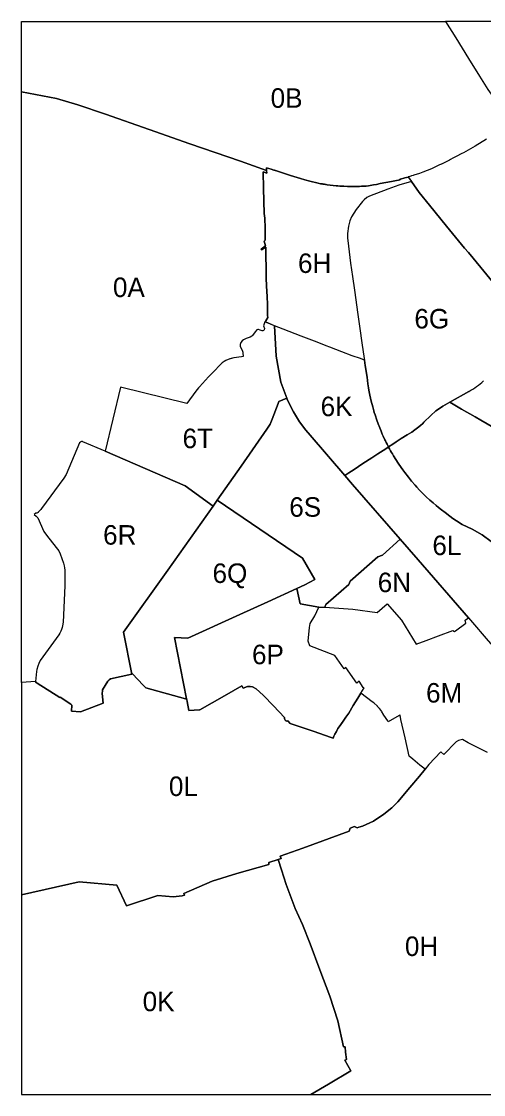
# Model space of a CAD drawing. Extents: x 152750 to 166250, y 378996 to 390000.
# Drawn here: x 152750 to 157492, y 379000 to 390000 of the extents above; entities that cross this region are included whole.
import ezdxf

# ---------------------------------------------------------------- set-up
doc = ezdxf.new("R2010")
doc.units = 0
doc.layers.add('BLT_Nummers', color=7, linetype='Continuous')
doc.layers.add('BLT_Shapes', color=7, linetype='Continuous')

msp = doc.modelspace()

# ---------------------------------------------------------------- linework, layer by layer
at = {"layer": 'BLT_Shapes'}
for p, q in [((163503, 390000), (157101, 390000)), ((157522, 388793), (157405, 388722)), ((157153, 388585), (157141, 388579)), ((157178, 388598), (157153, 388585)), ((156717, 388406), (156752, 388358)), ((156831, 388247), (156752, 388358)), ((155248, 386922), (155242, 386902)), ((155345, 386881), (155248, 386922)), ((155437, 386846), (155345, 386881)), ((155363, 386570), (155345, 386881)), ((155098, 386765), (155055, 386750)), ((155148, 386820), (155122, 386782)), ((155167, 386840), (155148, 386820)), ((155176, 386843), (155167, 386840)), ((155244, 386852), (155239, 386839)), ((155028, 386735), (155016, 386725)), ((155055, 386750), (155028, 386735)), ((155022, 386601), (155024, 386570)), ((154794, 386485), (154719, 386407)), ((154797, 386488), (154794, 386485)), ((154719, 386407), (154671, 386356)), ((153766, 386250), (153608, 385595)), ((156315, 386222), (156311, 386244)), ((157342, 386207), (157147, 386097)), ((157147, 386097), (157342, 386207)), ((156378, 385968), (156371, 385993)), ((157264, 386027), (157147, 386097)), ((157404, 385948), (157264, 386027)), ((157465, 385912), (157404, 385948)), ((156788, 385813), (156815, 385834)), ((156815, 385834), (156845, 385859)), ((153360, 385692), (153355, 385689)), ((153380, 385692), (153375, 385694)), ((153608, 385595), (153380, 385692)), ((156517, 385639), (156503, 385666)), ((156517, 385639), (156561, 385667)), ((156561, 385667), (156595, 385692)), ((153608, 385595), (154431, 385239)), ((156518, 385637), (156517, 385639)), ((153208, 385355), (153184, 385319)), ((156109, 385372), (156068, 385345)), ((156148, 385253), (156068, 385345)), ((156165, 385407), (156109, 385372)), ((156664, 385403), (156647, 385427)), ((154431, 385239), (154716, 385033)), ((156636, 384694), (156148, 385253)), ((156866, 385166), (156836, 385196)), ((156904, 385128), (156866, 385166)), ((156942, 385093), (156904, 385128)), ((154253, 384374), (154716, 385033)), ((154758, 385093), (154716, 385033)), ((154716, 385033), (154758, 385093)), ((155633, 384497), (154758, 385093)), ((154758, 385093), (155633, 384497)), ((156975, 385065), (156942, 385093)), ((152899, 384961), (152881, 384947)), ((152881, 384947), (152902, 384929)), ((152905, 384959), (152899, 384961)), ((152902, 384929), (152915, 384915)), ((152909, 384960), (152905, 384959)), ((152915, 384915), (152919, 384911)), ((157374, 384794), (157273, 384844)), ((157476, 384737), (157374, 384794)), ((156636, 384694), (156822, 384481)), ((156822, 384481), (156636, 384694)), ((157569, 384670), (157476, 384737)), ((156822, 384481), (157337, 383887)), ((157337, 383887), (156822, 384481)), ((153190, 384420), (153193, 384398)), ((153193, 384398), (153195, 384374)), ((153195, 384374), (153194, 384216)), ((153796, 383739), (154253, 384374)), ((156399, 383941), (156504, 384030)), ((154456, 383679), (154991, 383922)), ((155802, 383997), (155864, 383995)), ((155864, 383995), (156149, 383975)), ((156149, 383975), (156399, 383941)), ((157204, 383755), (157311, 383832)), ((157304, 383862), (157337, 383887)), ((157311, 383832), (157304, 383862)), ((157337, 383887), (157398, 383816)), ((153168, 383787), (153162, 383768)), ((153883, 383310), (153796, 383739)), ((157194, 383748), (157204, 383755)), ((152904, 383336), (152894, 383234)), ((153651, 383252), (153663, 383260)), ((153663, 383260), (153883, 383310)), ((153883, 383310), (153891, 383312)), ((155104, 383207), (155104, 383207)), ((153589, 383012), (153579, 383112)), ((154433, 383058), (154445, 383055)), ((153356, 382923), (153589, 383012))]:
    msp.add_line(p, q, dxfattribs=at)
for points in [[(157522, 388793), (157405, 388722), (157285, 388654), (157270, 388647), (157212, 388616), (157178, 388598), (157153, 388585), (157141, 388579), (157127, 388572), (157059, 388537), (157041, 388529), (156998, 388509), (156956, 388490), (156869, 388456), (156833, 388443), (156778, 388424), (156769, 388421), (156769, 388421), (156753, 388416), (156747, 388415), (156736, 388411), (156721, 388407), (156721, 388407), (156717, 388406), (156718, 388405), (156701, 388400), (156685, 388396), (156641, 388384), (156632, 388382), (156636, 388376), (156581, 388368), (156548, 388361), (156488, 388350), (156430, 388338), (156394, 388330), (156364, 388324), (156329, 388319), (156312, 388316), (156287, 388313), (156277, 388312), (156258, 388311), (156239, 388310), (156220, 388309), (156201, 388308), (156191, 388308), (156180, 388307), (156170, 388307), (156159, 388307), (156128, 388307), (156118, 388307), (156097, 388308), (156059, 388310), (156016, 388313), (155998, 388314), (155981, 388316), (155886, 388327), (155877, 388328), (155869, 388329), (155861, 388331), (155852, 388332), (155844, 388333), (155839, 388334), (155820, 388337), (155795, 388342), (155766, 388348), (155738, 388355), (155708, 388362), (155657, 388377), (155614, 388389), (155511, 388422), (155397, 388460), (155377, 388466), (155356, 388471), (155352, 388473), (155345, 388474), (155340, 388476), (155311, 388485), (155266, 388501), (155266, 388473), (154997, 388567), (154479, 388747), (154060, 388894), (153611, 389049), (153328, 389146), (153110, 389210), (152750, 389278), (152750, 390000), (157101, 390000), (157206, 389831), (157337, 389621), (157450, 389440), (157537, 389302)], [(157101, 390000), (157206, 389831), (157337, 389621), (157450, 389440), (157537, 389302), (157569, 389253), (157631, 389159), (157637, 389146), (157655, 389117), (157768, 388950)], [(157405, 388722), (157285, 388654), (157270, 388647), (157212, 388616), (157178, 388598)], [(157041, 388529), (157007, 388513), (156998, 388509), (156956, 388490)], [(157141, 388579), (157127, 388572), (157059, 388537), (157057, 388536), (157041, 388529)], [(156736, 388411), (156736, 388411), (156721, 388407), (156721, 388407), (156717, 388406)], [(156769, 388421), (156769, 388421), (156753, 388416), (156747, 388415), (156736, 388411)], [(156833, 388443), (156778, 388424), (156769, 388421)], [(156956, 388490), (156869, 388456), (156833, 388443)], [(156752, 388358), (156624, 388322), (156510, 388281), (156321, 388210), (156293, 388195), (156265, 388172), (156248, 388156), (156184, 388074), (156136, 387996), (156121, 387955), (156106, 387903), (156096, 387828), (156097, 387781), (156105, 387697), (156128, 387524), (156147, 387386), (156167, 387245), (156202, 386995), (156223, 386853), (156244, 386706), (156268, 386546), (156270, 386528)], [(156752, 388358), (156831, 388247), (156937, 388117), (157112, 387900), (157297, 387677), (157336, 387630), (157463, 387477), (157647, 387254), (157840, 387022), (158064, 386749), (158097, 386709), (158142, 386655)], [(157297, 387677), (157112, 387900), (156937, 388117), (156831, 388247)], [(157647, 387254), (157463, 387477), (157336, 387630), (157297, 387677)], [(155242, 386902), (155235, 386881), (155244, 386852)], [(155345, 386881), (155363, 386570), (155412, 386303), (155472, 386138)], [(155122, 386782), (155113, 386773), (155098, 386765)], [(155198, 386834), (155181, 386842), (155176, 386843)], [(155228, 386830), (155220, 386829), (155198, 386834)], [(155239, 386839), (155233, 386832), (155228, 386830)], [(156270, 386528), (156228, 386544), (156143, 386572), (156039, 386612), (155914, 386661), (155877, 386675), (155784, 386711), (155619, 386775), (155437, 386846)], [(154994, 386688), (154993, 386677), (154994, 386667), (155014, 386630), (155021, 386611), (155022, 386601)], [(155016, 386725), (155002, 386709), (154997, 386700), (154994, 386688)], [(154890, 386542), (154846, 386523), (154846, 386523), (154830, 386513)], [(154930, 386552), (154892, 386542), (154890, 386542)], [(155024, 386570), (155024, 386564), (155009, 386562), (154930, 386552)], [(155472, 386138), (155412, 386303), (155363, 386570)], [(154830, 386513), (154810, 386499), (154797, 386488)], [(156270, 386528), (156278, 386473), (156296, 386352), (156305, 386287), (156311, 386244), (156315, 386222), (156325, 386169), (156339, 386108), (156354, 386049), (156366, 386008), (156371, 385993), (156378, 385968), (156397, 385913), (156412, 385874), (156427, 385833), (156441, 385800), (156453, 385770), (156463, 385750), (156480, 385713), (156486, 385700), (156493, 385685), (156503, 385666), (156517, 385639)], [(156296, 386352), (156278, 386473), (156270, 386528)], [(154671, 386356), (154576, 386256), (154566, 386243), (154540, 386210), (154447, 386084), (154447, 386084), (153766, 386250)], [(156311, 386244), (156305, 386287), (156296, 386352)], [(156339, 386108), (156325, 386169), (156315, 386222)], [(155472, 386138), (155392, 386103), (155384, 386085), (155322, 385922), (155301, 385871), (155267, 385822), (155003, 385441), (154758, 385093)], [(155301, 385871), (155322, 385922), (155384, 386085), (155392, 386103), (155472, 386138)], [(155472, 386138), (155479, 386119), (155540, 385997), (155603, 385897), (155668, 385809), (155712, 385758), (156068, 385345)], [(155603, 385897), (155540, 385997), (155479, 386119), (155472, 386138)], [(156371, 385993), (156366, 386008), (156354, 386049), (156339, 386108)], [(157147, 386097), (157073, 386055), (157040, 386033), (157002, 386007), (156951, 385961), (156880, 385892), (156868, 385880), (156845, 385859), (156815, 385834), (156788, 385813), (156755, 385790), (156708, 385761), (156648, 385726), (156595, 385692), (156561, 385667), (156517, 385639)], [(156845, 385859), (156868, 385880), (156880, 385892), (156951, 385961), (157002, 386007), (157040, 386033)], [(157040, 386033), (157073, 386055), (157147, 386097)], [(157147, 386097), (157264, 386027), (157404, 385948), (157465, 385912), (157684, 385787), (157756, 385747), (157988, 385614), (158080, 385562), (158276, 385450), (158347, 385410), (158436, 385359), (158546, 385296), (158599, 385265), (158727, 385192), (158908, 385089), (159019, 385025), (159075, 384994)], [(156068, 385345), (155712, 385758), (155668, 385809), (155603, 385897)], [(156503, 385666), (156493, 385685), (156486, 385700), (156480, 385713), (156463, 385750), (156453, 385770), (156441, 385800), (156427, 385833), (156412, 385874), (156397, 385913), (156378, 385968)], [(157756, 385747), (157684, 385787), (157465, 385912)], [(154758, 385093), (155003, 385441), (155267, 385822), (155301, 385871)], [(156595, 385692), (156648, 385726), (156708, 385761), (156755, 385790), (156788, 385813)], [(153355, 385689), (153347, 385679), (153208, 385355)], [(153375, 385694), (153367, 385694), (153360, 385692)], [(154716, 385033), (154431, 385239), (153608, 385595)], [(156068, 385345), (156109, 385372), (156165, 385407), (156254, 385468), (156346, 385527), (156408, 385569), (156488, 385620), (156517, 385639)], [(156517, 385639), (156488, 385620), (156408, 385569), (156346, 385527), (156254, 385468), (156165, 385407)], [(156517, 385639), (156518, 385637), (156528, 385619), (156538, 385600), (156548, 385583), (156557, 385567), (156569, 385547), (156592, 385509), (156615, 385473), (156647, 385427), (156664, 385403), (156684, 385375), (156721, 385327), (156753, 385289), (156789, 385247), (156807, 385227), (156836, 385196), (156866, 385166), (156904, 385128), (156942, 385093), (156975, 385065), (157005, 385039), (157030, 385018), (157060, 384995), (157098, 384965), (157145, 384930), (157178, 384906), (157215, 384880), (157273, 384844), (157374, 384794), (157476, 384737), (157569, 384670)], [(156538, 385600), (156528, 385619), (156518, 385637)], [(156557, 385567), (156548, 385583), (156538, 385600)], [(156647, 385427), (156615, 385473), (156592, 385509), (156569, 385547), (156557, 385567)], [(156068, 385345), (156148, 385253), (156636, 384694)], [(156836, 385196), (156807, 385227), (156789, 385247), (156753, 385289), (156721, 385327), (156684, 385375), (156664, 385403)], [(153184, 385319), (152957, 385007), (152949, 384998)], [(154716, 385033), (154253, 384374), (153796, 383739), (153883, 383310)], [(157030, 385018), (157005, 385039), (156975, 385065)], [(157178, 384906), (157145, 384930), (157098, 384965), (157060, 384995), (157030, 385018)], [(152949, 384998), (152920, 384969), (152921, 384967), (152909, 384960)], [(152919, 384911), (152981, 384772), (153006, 384735)], [(157273, 384844), (157215, 384880), (157178, 384906)], [(153006, 384735), (153107, 384607), (153132, 384573), (153148, 384542)], [(156636, 384694), (156454, 384529), (156406, 384512), (156123, 384262), (156111, 384230), (155875, 384025), (155864, 383995)], [(156111, 384230), (156123, 384262), (156406, 384512), (156454, 384529), (156636, 384694)], [(153148, 384542), (153183, 384446), (153190, 384420)], [(155575, 384188), (155658, 384226), (155762, 384281), (155633, 384497)], [(155633, 384497), (155762, 384281), (155658, 384226), (155575, 384188)], [(153194, 384216), (153177, 383842), (153173, 383806), (153168, 383787)], [(155575, 384188), (155277, 384050), (154991, 383922), (154456, 383679), (154320, 383684), (154445, 383055)], [(154991, 383922), (155277, 384050), (155575, 384188)], [(155802, 383997), (155610, 384030), (155575, 384188)], [(155575, 384188), (155610, 384030), (155802, 383997)], [(155864, 383995), (155875, 384025), (156111, 384230)], [(157531, 382505), (157334, 382605), (157277, 382639), (157234, 382630), (157212, 382614), (157084, 382487), (157054, 382512), (156930, 382382), (156891, 382334), (156838, 382378), (156767, 382439), (156730, 382470), (156687, 382657), (156644, 382843), (156638, 382867), (156633, 382891), (156625, 382887), (156514, 382821), (156508, 382830), (156470, 382889), (156445, 382929), (156440, 382936), (156425, 382956), (156405, 382978), (156403, 382980), (156365, 383016), (156350, 383027), (156291, 383071), (156232, 383114), (156266, 383169), (156258, 383174), (156217, 383237), (156190, 383217), (156077, 383379), (156061, 383364), (155966, 383501), (155708, 383599), (155692, 383647), (155706, 383788), (155713, 383830), (155760, 383908), (155802, 383997), (155864, 383995), (156149, 383975), (156399, 383941), (156504, 384030), (156649, 383864), (156799, 383617), (156902, 383656), (157029, 383702), (157175, 383756), (157194, 383748), (157204, 383755), (157311, 383832), (157304, 383862), (157337, 383887), (157398, 383816), (157499, 383700)], [(156504, 384030), (156649, 383864), (156799, 383617)], [(157398, 383816), (157499, 383700), (157733, 383427)], [(153162, 383768), (153154, 383750), (153144, 383730), (153133, 383713), (152943, 383448), (152928, 383420), (152917, 383392), (152908, 383358), (152904, 383336)], [(154445, 383055), (154320, 383684), (154456, 383679)], [(156799, 383617), (156902, 383656), (157029, 383702)], [(157029, 383702), (157175, 383756), (157194, 383748)], [(153579, 383112), (153581, 383139), (153583, 383150), (153638, 383236), (153651, 383252)], [(153891, 383312), (154000, 383198), (154026, 383168), (154433, 383058)], [(152894, 383234), (152902, 383223), (152911, 383216)], [(152911, 383216), (153144, 383069), (153146, 383074), (153258, 383003), (153265, 382995), (153268, 382990), (153263, 382929), (153356, 382923)], [(157531, 382505), (157334, 382605), (157277, 382639), (157234, 382630), (157212, 382614), (157084, 382487), (157054, 382512), (156930, 382382), (156891, 382334), (156833, 382263), (156735, 382149), (156611, 382001), (156551, 381940), (156470, 381875), (156361, 381804), (156249, 381752), (156212, 381741), (156196, 381733), (156167, 381747), (156122, 381732), (156114, 381701), (155638, 381524), (155405, 381445), (155415, 381421), (155383, 381411), (155419, 381302), (155467, 381152), (155559, 380908), (155634, 380744), (155711, 380545), (155812, 380279), (155914, 380008), (155998, 379755), (156053, 379488), (156071, 379490), (156075, 379435), (156087, 379360), (156070, 379351), (156129, 379242), (155900, 379108), (155718, 379000), (157973, 379000)]]:
    msp.add_lwpolyline(points, dxfattribs=at)
for points in [[(155266, 388473), (155267, 388444), (155230, 388457), (155234, 388286), (155241, 388033), (155247, 387984), (155250, 387882), (155252, 387814), (155252, 387758), (155239, 387749), (155253, 387699), (155209, 387665), (155213, 387659), (155258, 387687), (155259, 387587), (155260, 387482), (155261, 387372), (155263, 387286), (155271, 387181), (155274, 387100), (155274, 386987), (155277, 386966), (155259, 386931), (155253, 386921), (155248, 386922), (155242, 386902), (155235, 386881), (155244, 386852), (155239, 386839), (155233, 386832), (155228, 386830), (155220, 386829), (155198, 386834), (155181, 386842), (155176, 386843), (155167, 386840), (155148, 386820), (155122, 386782), (155113, 386773), (155098, 386765), (155055, 386750), (155028, 386735), (155016, 386725), (155002, 386709), (154997, 386700), (154994, 386688), (154993, 386677), (154994, 386667), (155014, 386630), (155021, 386611), (155022, 386601), (155024, 386570), (155024, 386564), (155009, 386562), (154930, 386552), (154890, 386542), (154846, 386523), (154846, 386523), (154830, 386513), (154810, 386499), (154797, 386488), (154794, 386485), (154719, 386407), (154671, 386356), (154576, 386256), (154566, 386243), (154540, 386210), (154447, 386084), (153766, 386250), (153608, 385595), (153380, 385692), (153375, 385694), (153367, 385694), (153360, 385692), (153355, 385689), (153347, 385679), (153208, 385355), (153184, 385319), (152957, 385007), (152949, 384998), (152920, 384969), (152921, 384967), (152909, 384960), (152905, 384959), (152899, 384961), (152881, 384947), (152902, 384929), (152915, 384915), (152919, 384911), (152981, 384772), (153006, 384735), (153107, 384607), (153132, 384573), (153148, 384542), (153183, 384446), (153190, 384420), (153193, 384398), (153195, 384374), (153194, 384216), (153177, 383842), (153173, 383806), (153168, 383787), (153162, 383768), (153154, 383750), (153144, 383730), (153133, 383713), (152943, 383448), (152928, 383420), (152917, 383392), (152908, 383358), (152904, 383336), (152894, 383234), (152750, 383224), (152750, 389278), (153110, 389210), (153328, 389146), (153611, 389049), (154060, 388894), (154479, 388747), (154997, 388567)], [(155259, 386931), (155277, 386966), (155274, 386987), (155274, 387100), (155271, 387181), (155263, 387286), (155261, 387372), (155260, 387482), (155259, 387587), (155258, 387687), (155213, 387659), (155209, 387665), (155253, 387699), (155239, 387749), (155252, 387758), (155252, 387814), (155250, 387882), (155247, 387984), (155241, 388033), (155234, 388286), (155230, 388457), (155267, 388444), (155266, 388473), (155266, 388501), (155311, 388485), (155340, 388476), (155345, 388474), (155352, 388473), (155356, 388471), (155377, 388466), (155397, 388460), (155511, 388422), (155614, 388389), (155657, 388377), (155708, 388362), (155738, 388355), (155766, 388348), (155795, 388342), (155820, 388337), (155839, 388334), (155844, 388333), (155852, 388332), (155861, 388331), (155869, 388329), (155877, 388328), (155886, 388327), (155981, 388316), (155998, 388314), (156016, 388313), (156059, 388310), (156097, 388308), (156118, 388307), (156128, 388307), (156159, 388307), (156170, 388307), (156180, 388307), (156191, 388308), (156201, 388308), (156220, 388309), (156239, 388310), (156258, 388311), (156277, 388312), (156287, 388313), (156312, 388316), (156329, 388319), (156364, 388324), (156394, 388330), (156430, 388338), (156488, 388350), (156548, 388361), (156581, 388368), (156636, 388376), (156632, 388382), (156641, 388384), (156685, 388396), (156701, 388400), (156718, 388405), (156752, 388358), (156624, 388322), (156510, 388281), (156321, 388210), (156293, 388195), (156265, 388172), (156248, 388156), (156184, 388074), (156136, 387996), (156121, 387955), (156106, 387903), (156096, 387828), (156097, 387781), (156105, 387697), (156128, 387524), (156147, 387386), (156167, 387245), (156202, 386995), (156223, 386853), (156244, 386706), (156268, 386546), (156270, 386528), (156228, 386544), (156143, 386572), (156039, 386612), (155914, 386661), (155877, 386675), (155784, 386711), (155619, 386775), (155437, 386846), (155345, 386881), (155253, 386921)], [(155096, 383184), (155121, 383180), (155158, 383158), (155229, 383094), (155235, 383089), (155335, 382984), (155450, 382864), (155450, 382861), (155450, 382858), (155450, 382854), (155450, 382851), (155451, 382847), (155453, 382843), (155455, 382839), (155459, 382835), (155463, 382832), (155468, 382831), (155473, 382829), (155477, 382829), (155478, 382829), (155483, 382830), (155508, 382804), (155559, 382787), (155753, 382720), (155917, 382664), (155947, 382654), (155957, 382674), (155967, 382694), (155967, 382694), (155983, 382722), (155998, 382751), (156020, 382782), (156042, 382813), (156044, 382816), (156080, 382869), (156108, 382910), (156155, 382987), (156202, 383064), (156232, 383114), (156266, 383169), (156258, 383174), (156217, 383237), (156190, 383217), (156077, 383379), (156061, 383364), (155966, 383501), (155708, 383599), (155692, 383647), (155706, 383788), (155713, 383830), (155760, 383908), (155802, 383997), (155610, 384030), (155575, 384188), (155277, 384050), (154991, 383922), (154456, 383679), (154320, 383684), (154445, 383055), (154446, 383049), (154450, 383028), (154468, 382937), (154578, 382943), (154579, 382944), (154834, 383087), (155012, 383189), (155026, 383164), (155071, 383183)], [(155383, 381411), (155415, 381421), (155405, 381445), (155638, 381524), (156114, 381701), (156122, 381732), (156167, 381747), (156196, 381733), (156212, 381741), (156249, 381752), (156361, 381804), (156470, 381875), (156551, 381940), (156611, 382001), (156735, 382149), (156833, 382263), (156891, 382334), (156838, 382378), (156767, 382439), (156730, 382470), (156687, 382657), (156644, 382843), (156638, 382867), (156633, 382891), (156625, 382887), (156514, 382821), (156508, 382830), (156470, 382889), (156445, 382929), (156440, 382936), (156425, 382956), (156405, 382978), (156403, 382980), (156365, 383016), (156350, 383027), (156291, 383071), (156232, 383114), (156202, 383064), (156155, 382987), (156108, 382910), (156080, 382869), (156044, 382816), (156020, 382782), (155998, 382751), (155983, 382722), (155967, 382694), (155967, 382694), (155957, 382674), (155947, 382654), (155917, 382664), (155753, 382720), (155559, 382787), (155508, 382804), (155483, 382830), (155478, 382829), (155477, 382829), (155473, 382829), (155468, 382831), (155463, 382832), (155459, 382835), (155455, 382839), (155453, 382843), (155451, 382847), (155450, 382851), (155450, 382854), (155450, 382858), (155450, 382861), (155450, 382864), (155335, 382984), (155235, 383089), (155229, 383094), (155158, 383158), (155121, 383180), (155096, 383184), (155071, 383183), (155026, 383164), (155012, 383189), (154834, 383087), (154579, 382944), (154578, 382943), (154468, 382937), (154450, 383028), (154446, 383049), (154445, 383055), (154433, 383058), (154026, 383168), (154000, 383198), (153891, 383312), (153883, 383310), (153663, 383260), (153651, 383252), (153638, 383236), (153583, 383150), (153581, 383139), (153579, 383112), (153589, 383012), (153356, 382923), (153263, 382929), (153268, 382990), (153265, 382995), (153258, 383003), (153146, 383074), (153144, 383069), (152911, 383216), (152902, 383223), (152894, 383234), (152750, 383224), (152750, 381046), (153343, 381180), (153728, 381146), (153828, 380935), (154151, 381040), (154308, 381028), (154398, 381036), (154422, 381044), (154417, 381060), (154707, 381186), (154959, 381267), (155288, 381357), (155289, 381379)], [(155383, 381411), (155289, 381379), (155288, 381357), (154959, 381267), (154707, 381186), (154417, 381060), (154422, 381044), (154398, 381036), (154308, 381028), (154151, 381040), (153828, 380935), (153728, 381146), (153343, 381180), (152750, 381046), (152750, 379000), (155718, 379000), (155900, 379108), (156129, 379242), (156070, 379351), (156087, 379360), (156075, 379435), (156071, 379490), (156053, 379488), (155998, 379755), (155914, 380008), (155812, 380279), (155711, 380545), (155634, 380744), (155559, 380908), (155467, 381152), (155419, 381302)]]:
    msp.add_lwpolyline(points, close=True, dxfattribs=at)
msp.add_arc((156920, 386951), 855, 299.5873, 311.9452, dxfattribs=at)
msp.add_arc((156920, 386951), 855, 299.5873, 311.9452, dxfattribs=at)

# ---------------------------------------------------------------- texts
at = {"layer": 'BLT_Nummers'}
for s, p in [('0B', (155307, 389115)), ('6H', (155588, 387422)), ('0A', (153689, 387175)), ('6G', (156782, 386853)), ('6K', (155820, 385954)), ('6T', (154403, 385626)), ('6S', (155498, 384923)), ('6R', (153588, 384637)), ('6L', (156967, 384530)), ('6Q', (154711, 384244)), ('6N', (156406, 384150)), ('6P', (155116, 383411)), ('6M', (156902, 383018)), ('0L', (154263, 382060)), ('0H', (156685, 380420)), ('0K', (153994, 379854))]:
    msp.add_text(s, height=200, dxfattribs=at).set_placement(p)

doc.saveas('drawing.dxf')
